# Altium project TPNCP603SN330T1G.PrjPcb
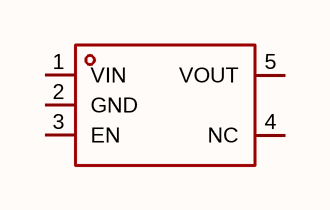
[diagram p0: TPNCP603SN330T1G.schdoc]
1 sheet, 1 parts. Net scope: global (net labels, ports and power ports of the same name join across sheets).

## Sheet TPNCP603SN330T1G.schdoc
size 127 x 101 mm

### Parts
U?  tpncp603sn330t1g  [SOT-23-5_L2.9-W1.6-P0.95-LS2.8-BR]  (value not drawn)

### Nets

Not connected (* = marked no-connect by the designer): U? 1(VIN) 2(GND) 3(EN) 4(NC) 5(VOUT)

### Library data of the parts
U? = tpncp603sn330t1g: 输出极性:正极;工作电压:5.5V;输出电压:3.3V;输出电流:300mA;电源纹波抑制比(PSRR):-;输出类型:固定;; Manufacturer: TECH PUBLIC(台舟); AddInBom: yes; ModelId: 7ba65df16e7b4570af156e925f9c37fe; ModelTransform: 114.173,114.173,0,90,0,0,0,0,0; Output Configuration: 正极; Voltage - Supply: 5.5V; Output Voltage: 3.3V; Output Current: 300mA; Voltage Dropout: 180mV@(300mA); standby current: 30uA; Output Type: 固定; Number of Outputs: 1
